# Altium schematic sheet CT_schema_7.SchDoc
size 277 x 170 mm
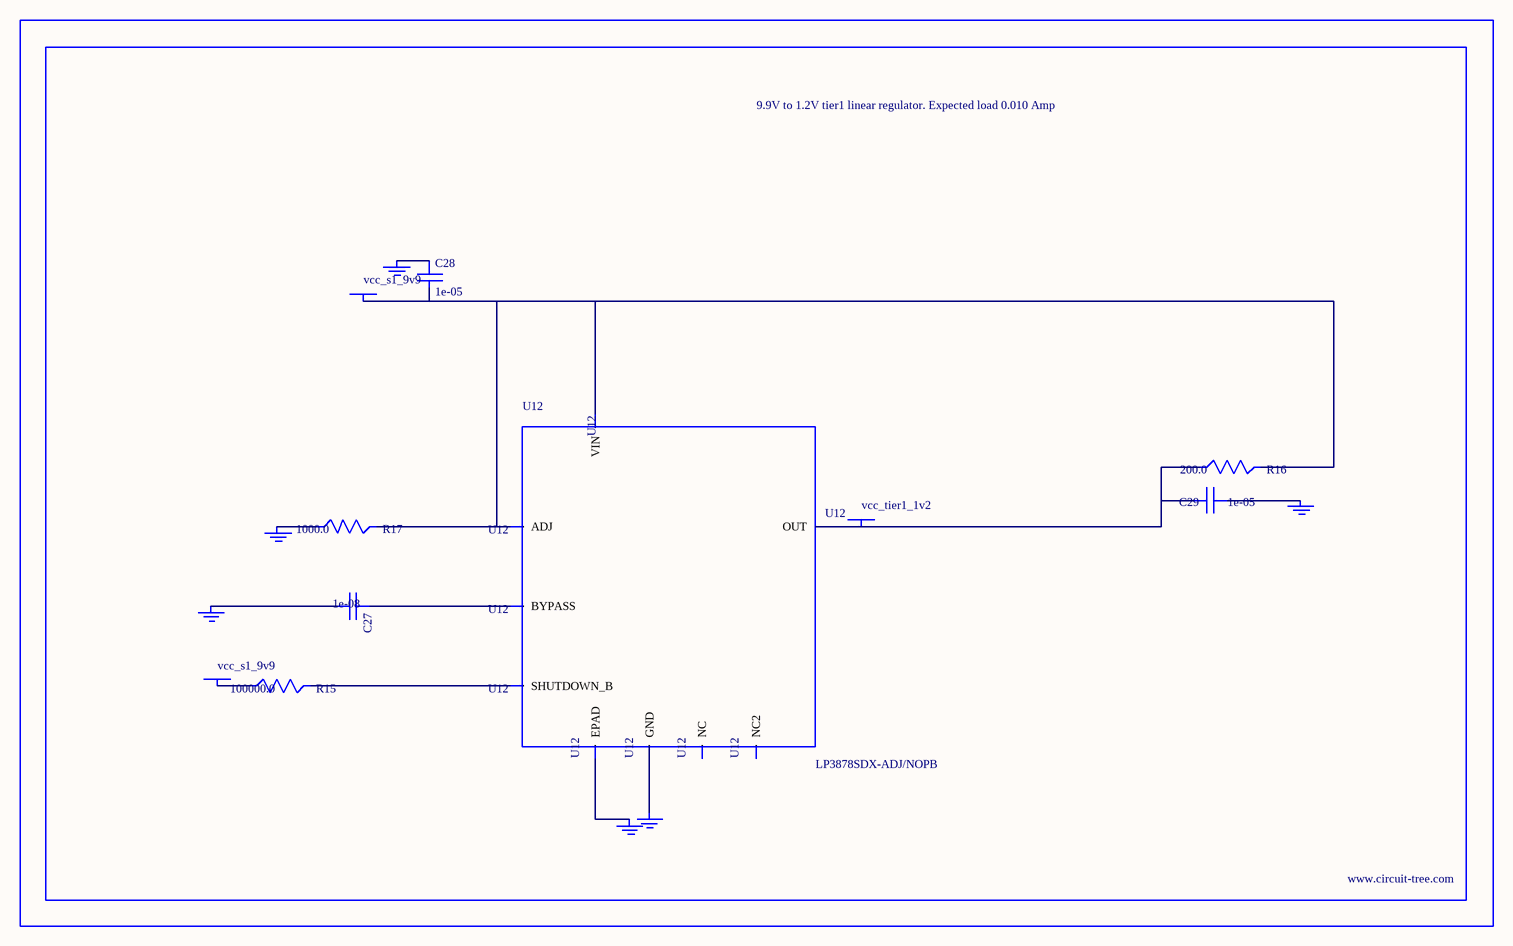
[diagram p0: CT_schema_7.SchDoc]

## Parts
BORDER6  (no value)
C27  1e-08  [C0402]
C28  1e-05  [C1206]
C29  1e-05  [C0805]
GND_INSTANCE_6_0  (no value)
GND_INSTANCE_6_1  (no value)
GND_INSTANCE_6_2  (no value)
GND_INSTANCE_6_3  (no value)
GND_INSTANCE_6_4  (no value)
GND_INSTANCE_6_5  (no value)
POWER_INSTANCE_6_0  vcc_s1_9v9
POWER_INSTANCE_6_1  vcc_s1_9v9
POWER_INSTANCE_6_2  vcc_tier1_1v2
R15  100000.0  [R0603]
R16  200.0  [R0603]
R17  1000.0  [R0603]
U12  LP3878SDX-ADJ/NOPB  [WSON-8]

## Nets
NetC27_1: C27.1 U12.1(BYPASS)
NetC27_2: C27.2 GND_INSTANCE_6_0.0(GND)
NetC28_1: C28.1 GND_INSTANCE_6_1.0(GND)
NetC28_2: C28.2 POWER_INSTANCE_6_0.0(PWR) R16.2 R17.2 U12.4(VIN) U12.6(ADJ)
NetC29_1: C29.1 GND_INSTANCE_6_2.0(GND)
NetC29_2: C29.2 POWER_INSTANCE_6_2.0(PWR) R16.1 U12.5(OUT)
NetGND_INSTANCE_6_3_0: GND_INSTANCE_6_3.0(GND) R17.1
NetGND_INSTANCE_6_4_0: GND_INSTANCE_6_4.0(GND) U12.PAD(EPAD)
NetGND_INSTANCE_6_5_0: GND_INSTANCE_6_5.0(GND) U12.3(GND)
NetPOWER_INSTANCE_6_1_0: POWER_INSTANCE_6_1.0(PWR) R15.1
NetR15_2: R15.2 U12.8(SHUTDOWN_B)

Not connected (* = marked no-connect by the designer): U12 2(NC) 7(NC2)

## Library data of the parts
BORDER6 = BORDER_PAGE6
C27 = C0402C103K3RAC
C28 = C1206C106K3RACTU
C29 = GRM219R60J106ME19D
GND_INSTANCE_6_0-GND_INSTANCE_6_5 = GND
POWER_INSTANCE_6_0-POWER_INSTANCE_6_2 = PWR
R15 = RC0603JR-07100KL
R16 = RC0603JR-07200RL
R17 = RC0603JR-071KL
